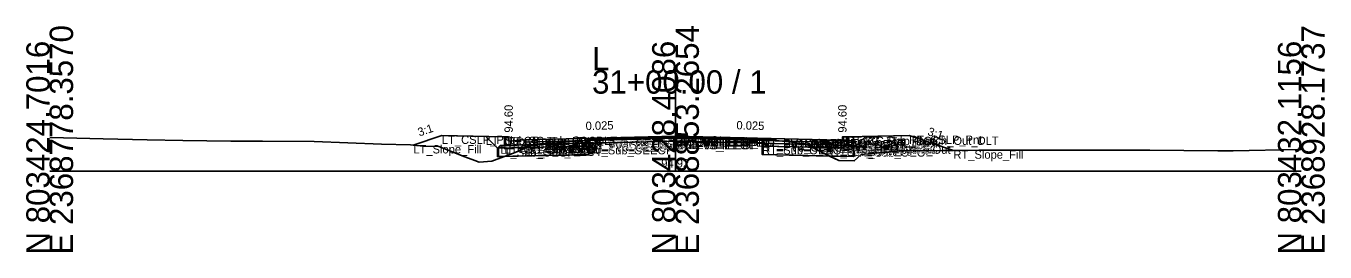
# Model space of a CAD drawing. Extents: x -26 to 8153, y -10 to 9520.
# Drawn here: x 1997.2 to 2152.8, y 4490.3 to 4517.4 of the extents above; entities that cross this region are included whole.
import ezdxf

# ---------------------------------------------------------------- set-up
doc = ezdxf.new("R2010")
doc.units = 0
for name, color, linetype in [('Exist CMT Pavement', 7, 'Continuous'), ('Exist Cross Section Cell', 7, 'Continuous'), ('Exist XS Center Line Elevation Label', 7, 'Continuous'), ('Exist XS Ground Line', 7, 'Continuous'), ('Prop CMT Conc Surface', 7, 'Continuous'), ('Prop CMT Concrete Structures', 7, 'Continuous'), ('Prop CMT Pvmt Course 1', 7, 'Continuous'), ('Prop CMT Pvmt Course 1 CG', 7, 'Continuous'), ('Prop CMT Pvmt Course 1 Wedge', 7, 'Continuous'), ('Prop CMT Pvmt Course 2', 7, 'Continuous'), ('Prop CMT Pvmt Course 2 Wedge', 7, 'Continuous'), ('Prop CMT Pvmt Course 3', 7, 'Continuous'), ('Prop CMT Pvmt Course 3 Wedge', 7, 'Continuous'), ('Prop CMT Pvmt Surface', 7, 'Continuous'), ('Prop CMT Pvmt Wedge Surface 1', 7, 'Continuous'), ('Prop CMT Pvmt Wedge Surface 2', 7, 'Continuous'), ('Prop CMT Pvmt Wedge Surface 3', 7, 'Continuous'), ('Prop CMT Shallow Undercut', 7, 'Continuous'), ('Prop CMT Shallow Undercut Boundary', 7, 'Continuous'), ('Prop CMT Slope Grass', 7, 'Continuous'), ('Prop CMT Subgrade Earthwork', 7, 'Continuous'), ('Prop XS Earthwork Shape', 7, 'Continuous'), ('Prop XS Hydro Elevations', 7, 'Continuous'), ('Prop XS SE Text', 7, 'Continuous'), ('Prop XS Side Slope Text', 7, 'Continuous'), ('Prop XS Subgrade Earthwork', 7, 'Continuous'), ('Scratch_Level_2', 7, 'Continuous'), ('Scratch_Level_6', 7, 'Continuous')]:
    doc.layers.add(name, color=color, linetype=linetype)

msp = doc.modelspace()

# ---------------------------------------------------------------- linework, layer by layer
at = {"layer": 'Exist CMT Pavement'}
for p, q in [((2068.35, 4503.79), (2074.82, 4503.93)), ((2074.82, 4503.93), (2077.37, 4503.91)), ((2077.37, 4503.91), (2085.38, 4503.83)), ((2064.58, 4503.69), (2068.35, 4503.79))]:
    msp.add_line(p, q, dxfattribs=at)
at = {"layer": 'Exist Cross Section Cell'}
for p, q in [((2075, 4500), (2075, 4512.07)), ((2000, 4500), (2075, 4500)), ((2075, 4500), (2150, 4500))]:
    msp.add_line(p, q, dxfattribs=at)
at = {"layer": 'Exist XS Ground Line'}
for p, q in [((2000, 4504.02), (2001.67, 4503.98)), ((2001.67, 4503.98), (2006.42, 4503.85)), ((2068.35, 4503.79), (2074.82, 4503.93)), ((2074.82, 4503.93), (2077.37, 4503.91)), ((2077.37, 4503.91), (2085.38, 4503.83)), ((2006.42, 4503.85), (2011.68, 4503.73)), ((2011.68, 4503.73), (2015.96, 4503.67)), ((2015.96, 4503.67), (2021.69, 4503.58)), ((2021.69, 4503.58), (2025.5, 4503.59)), ((2025.5, 4503.59), (2031.71, 4503.53)), ((2031.71, 4503.53), (2039.76, 4503.23)), ((2039.76, 4503.23), (2043.23, 4503.14)), ((2043.23, 4503.14), (2044.8, 4503)), ((2044.8, 4503), (2046.63, 4502.95)), ((2046.63, 4502.95), (2049.77, 4501.7)), ((2055.77, 4502.23), (2058.1, 4503.24)), ((2058.1, 4503.24), (2060.75, 4503.39)), ((2060.75, 4503.39), (2064.58, 4503.69)), ((2064.58, 4503.69), (2068.35, 4503.79)), ((2085.38, 4503.83), (2087.83, 4503.59)), ((2087.83, 4503.59), (2089.28, 4503.42)), ((2089.28, 4503.42), (2090.58, 4503.27)), ((2090.58, 4503.27), (2092.09, 4502.48)), ((2092.09, 4502.48), (2094.58, 4501.26)), ((2097.23, 4501.99), (2101.8, 4502.42)), ((2101.8, 4502.42), (2102.44, 4502.42)), ((2102.44, 4502.42), (2111.37, 4502.51)), ((2111.37, 4502.51), (2111.81, 4502.52)), ((2111.81, 4502.52), (2120.91, 4502.49)), ((2120.91, 4502.49), (2121.82, 4502.5)), ((2121.82, 4502.5), (2130.45, 4502.52)), ((2130.45, 4502.52), (2131.83, 4502.52)), ((2131.83, 4502.52), (2139.99, 4502.42)), ((2139.99, 4502.42), (2141.85, 4502.41)), ((2141.85, 4502.41), (2149.53, 4502.57)), ((2149.53, 4502.57), (2150, 4502.57)), ((2049.77, 4501.7), (2050.97, 4501.28)), ((2050.97, 4501.28), (2051.48, 4501.08)), ((2051.48, 4501.08), (2052.98, 4501.19)), ((2052.98, 4501.19), (2055.77, 4502.23)), ((2094.58, 4501.26), (2096.43, 4501.22)), ((2096.43, 4501.22), (2097.23, 4501.99))]:
    msp.add_line(p, q, dxfattribs=at)
at = {"layer": 'Prop CMT Conc Surface'}
for points in [[(2055, 4503.6), (2055, 4504.1), (2054.5, 4504.1)], [(2095, 4503.6), (2095, 4504.1), (2095.5, 4504.1)], [(2057, 4503.73), (2055, 4503.6)], [(2093, 4503.73), (2095, 4503.6)]]:
    msp.add_lwpolyline(points, dxfattribs=at)
at = {"layer": 'Prop CMT Concrete Structures'}
for points in [[(2057, 4503.73), (2055, 4503.6), (2055, 4504.1), (2054.5, 4504.1)], [(2054.5, 4504.1), (2054.5, 4503.08), (2057, 4503.14)], [(2093, 4503.73), (2095, 4503.6), (2095, 4504.1), (2095.5, 4504.1)], [(2095.5, 4504.1), (2095.5, 4503.08), (2093, 4503.14)], [(2057, 4503.14), (2057, 4503.73)], [(2093, 4503.14), (2093, 4503.73)]]:
    msp.add_lwpolyline(points, dxfattribs=at)
at = {"layer": 'Prop CMT Pvmt Course 1'}
for points in [[(2075, 4504.18), (2057, 4503.73)], [(2064.58, 4503.79), (2075, 4504.05)], [(2075, 4503.93), (2075, 4504.18)], [(2075, 4504.18), (2093, 4503.73)], [(2075, 4503.93), (2075, 4504.18)], [(2075, 4504.05), (2075, 4503.93), (2075, 4503.93)], [(2085.38, 4503.79), (2075, 4504.05)], [(2075, 4504.05), (2075, 4503.93), (2075, 4503.93)], [(2057, 4503.73), (2057, 4503.48)], [(2057, 4503.48), (2064.58, 4503.67)], [(2064.58, 4503.67), (2064.58, 4503.79)], [(2085.38, 4503.67), (2085.38, 4503.79)], [(2093, 4503.48), (2085.38, 4503.67)], [(2093, 4503.73), (2093, 4503.48)]]:
    msp.add_lwpolyline(points, dxfattribs=at)
at = {"layer": 'Prop CMT Pvmt Course 1 CG'}
for points in [[(2057, 4503.14), (2054, 4503.07), (2053.66, 4502.73)], [(2053.66, 4502.73), (2057, 4502.81)], [(2057, 4502.81), (2057, 4503.14)], [(2093, 4503.14), (2096, 4503.07), (2096.34, 4502.73)], [(2093, 4502.81), (2093, 4503.14)], [(2096.34, 4502.73), (2093, 4502.81)]]:
    msp.add_lwpolyline(points, dxfattribs=at)
at = {"layer": 'Prop CMT Pvmt Course 1 Wedge'}
for points in [[(2075, 4504.05), (2064.58, 4503.79)], [(2075, 4504.05), (2085.38, 4503.79)]]:
    msp.add_lwpolyline(points, dxfattribs=at)
at = {"layer": 'Prop CMT Pvmt Course 2'}
for points in [[(2064.58, 4503.67), (2057, 4503.48)], [(2057, 4503.48), (2057, 4503.15)], [(2057, 4503.15), (2064.58, 4503.34)], [(2064.58, 4503.34), (2064.58, 4503.67)], [(2085.38, 4503.34), (2085.38, 4503.67)], [(2085.38, 4503.67), (2093, 4503.48)], [(2093, 4503.15), (2085.38, 4503.34)], [(2093, 4503.48), (2093, 4503.15)]]:
    msp.add_lwpolyline(points, dxfattribs=at)
at = {"layer": 'Prop CMT Pvmt Course 2 Wedge'}
for points in [[(2075, 4503.93), (2064.58, 4503.67)], [(2075, 4503.93), (2085.38, 4503.67)]]:
    msp.add_lwpolyline(points, dxfattribs=at)
at = {"layer": 'Prop CMT Pvmt Course 3'}
for points in [[(2064.58, 4503.34), (2057, 4503.15)], [(2057, 4503.15), (2057, 4502.81)], [(2057, 4502.81), (2064.58, 4503)], [(2064.58, 4503), (2064.58, 4503.34)], [(2085.38, 4503.34), (2093, 4503.15)], [(2085.38, 4503), (2085.38, 4503.34)], [(2093, 4502.81), (2085.38, 4503)], [(2093, 4503.15), (2093, 4502.81)]]:
    msp.add_lwpolyline(points, dxfattribs=at)
at = {"layer": 'Prop CMT Pvmt Course 3 Wedge'}
for points in [[(2075, 4503.6), (2064.58, 4503.34)], [(2075, 4503.6), (2085.38, 4503.34)]]:
    msp.add_lwpolyline(points, dxfattribs=at)
at = {"layer": 'Prop CMT Pvmt Surface'}
for points in [[(2075, 4504.18), (2057, 4503.73)], [(2075, 4504.18), (2093, 4503.73)]]:
    msp.add_lwpolyline(points, dxfattribs=at)
at = {"layer": 'Prop CMT Pvmt Wedge Surface 1'}
for points in [[(2075, 4504.05), (2064.58, 4503.79)], [(2075, 4504.05), (2085.38, 4503.79)], [(2057, 4503.48), (2057, 4503.73)], [(2064.58, 4503.67), (2057, 4503.48)], [(2064.58, 4503.79), (2064.58, 4503.67)], [(2085.38, 4503.79), (2085.38, 4503.67)], [(2085.38, 4503.67), (2093, 4503.48)], [(2093, 4503.48), (2093, 4503.73)]]:
    msp.add_lwpolyline(points, dxfattribs=at)
at = {"layer": 'Prop CMT Pvmt Wedge Surface 2'}
for points in [[(2075, 4503.93), (2057, 4503.48)], [(2075, 4503.93), (2093, 4503.48)], [(2057, 4503.48), (2057, 4503.73)], [(2093, 4503.48), (2093, 4503.73)]]:
    msp.add_lwpolyline(points, dxfattribs=at)
at = {"layer": 'Prop CMT Pvmt Wedge Surface 3'}
for points in [[(2057, 4503.15), (2057, 4503.73)], [(2075, 4503.6), (2057, 4503.15)], [(2075, 4503.6), (2093, 4503.15)], [(2093, 4503.15), (2093, 4503.73)]]:
    msp.add_lwpolyline(points, dxfattribs=at)
at = {"layer": 'Prop CMT Shallow Undercut'}
for points in [[(2064.58, 4503), (2064.58, 4502), (2054.48, 4501.75), (2055.77, 4502.23), (2057.12, 4502.82)], [(2093.46, 4501.8), (2085.38, 4502), (2085.38, 4503), (2091.37, 4502.85), (2092.09, 4502.48)]]:
    msp.add_lwpolyline(points, close=True, dxfattribs=at)
at = {"layer": 'Prop CMT Shallow Undercut Boundary'}
for p, q in [((2053.66, 4502.73), (2064.58, 4503)), ((2053.66, 4502.73), (2053.66, 4501.73)), ((2064.58, 4503), (2064.58, 4502)), ((2085.38, 4503), (2085.38, 4502)), ((2085.38, 4503), (2096.34, 4502.73)), ((2096.34, 4502.73), (2096.34, 4501.73)), ((2064.58, 4502), (2053.66, 4501.73)), ((2096.34, 4501.73), (2085.38, 4502))]:
    msp.add_line(p, q, dxfattribs=at)
at = {"layer": 'Prop CMT Slope Grass'}
for points in [[(2054.5, 4504.1), (2047, 4504.25), (2043.58, 4503.11)], [(2095.5, 4504.1), (2103, 4504.25), (2108.3, 4502.48)]]:
    msp.add_lwpolyline(points, dxfattribs=at)
at = {"layer": 'Prop CMT Subgrade Earthwork'}
for points in [[(2057, 4502.81), (2053.66, 4502.73), (2052.25, 4504.14)], [(2093, 4502.81), (2096.34, 4502.73), (2097.75, 4504.14)], [(2064.58, 4503), (2057, 4502.81)], [(2064.58, 4503), (2064.6, 4503.69)], [(2085.38, 4503), (2085.37, 4503.83)], [(2085.38, 4503), (2093, 4502.81)]]:
    msp.add_lwpolyline(points, dxfattribs=at)
at = {"layer": 'Prop XS Earthwork Shape'}
for points in [[(2046.63, 4502.95), (2049.77, 4501.7), (2050.97, 4501.28), (2051.48, 4501.08), (2052.98, 4501.19), (2054.48, 4501.75), (2053.66, 4501.73), (2053.66, 4502.73), (2052.25, 4504.14), (2047, 4504.25), (2043.58, 4503.11), (2044.8, 4503)], [(2097.23, 4501.99), (2101.8, 4502.42), (2102.44, 4502.42), (2108.3, 4502.48), (2103, 4504.25), (2097.75, 4504.14), (2096.34, 4502.73), (2096.34, 4501.73), (2093.46, 4501.8), (2094.58, 4501.26), (2096.43, 4501.22)], [(2054.48, 4501.75), (2053.66, 4501.73), (2053.66, 4502.73), (2057, 4502.81), (2057.12, 4502.82), (2055.77, 4502.23)], [(2054.48, 4501.75), (2055.77, 4502.23), (2057.12, 4502.82), (2064.58, 4503), (2064.58, 4502)], [(2060.75, 4503.39), (2064.58, 4503.69), (2064.6, 4503.69), (2064.58, 4503), (2057.12, 4502.82), (2058.1, 4503.24)], [(2085.38, 4503), (2091.37, 4502.85), (2090.58, 4503.27), (2089.28, 4503.42), (2087.83, 4503.59), (2085.38, 4503.83), (2085.37, 4503.83)], [(2085.38, 4503), (2091.37, 4502.85), (2092.09, 4502.48), (2093.46, 4501.8), (2085.38, 4502)], [(2091.37, 4502.85), (2092.09, 4502.48), (2093.46, 4501.8), (2096.34, 4501.73), (2096.34, 4502.73), (2093, 4502.81)]]:
    msp.add_lwpolyline(points, close=True, dxfattribs=at)
at = {"layer": 'Prop XS Subgrade Earthwork'}
for p, q in [((2053.66, 4502.73), (2064.58, 4503)), ((2085.38, 4503), (2096.34, 4502.73))]:
    msp.add_line(p, q, dxfattribs=at)
at = {"layer": 'Scratch_Level_6'}
for points in [[(2064.58, 4503), (2064.58, 4502), (2054.48, 4501.75), (2055.77, 4502.23), (2057.12, 4502.82)], [(2093.46, 4501.8), (2085.38, 4502), (2085.38, 4503), (2091.37, 4502.85), (2092.09, 4502.48)]]:
    msp.add_lwpolyline(points, close=True, dxfattribs=at)

# ---------------------------------------------------------------- texts
at = {"layer": 'Exist Cross Section Cell'}
for s, p in [('E 2368778.3570', (2002.8, 4490)), ('E 2368853.2654', (2077.8, 4490)), ('E 2368928.1737', (2152.8, 4490)), ('N 803424.7016', (2000, 4490)), ('N 803428.4086', (2075, 4490)), ('N 803432.1156', (2150, 4490))]:
    msp.add_text(s, height=2.8, rotation=90, dxfattribs=at).set_placement(p)
for s, p in [('L', (2065, 4512.07)), ('31+00.00 / 1', (2065, 4509.27))]:
    msp.add_text(s, height=2.8, dxfattribs=at).set_placement(p)
at = {"layer": 'Exist XS Center Line Elevation Label'}
msp.add_text('94.92', height=1, dxfattribs=at).set_placement((2073.29, 4500.42))
at = {"layer": 'Prop XS Hydro Elevations'}
for p in [(2055.5, 4504.6), (2095.5, 4504.6)]:
    msp.add_text('94.60', height=1, rotation=90, dxfattribs=at).set_placement(p)
at = {"layer": 'Prop XS SE Text'}
for rotation, p in [(1.4321, (2064.24, 4504.91)), (358.5679, (2082.29, 4505))]:
    msp.add_text('0.025', height=1, rotation=rotation, dxfattribs=at).set_placement(p)
at = {"layer": 'Prop XS Side Slope Text'}
for rotation, p in [(18.4349, (2044.3, 4504.14)), (341.5651, (2105.13, 4504.33))]:
    msp.add_text('3:1', height=1, rotation=rotation, dxfattribs=at).set_placement(p)
at = {"layer": 'Scratch_Level_2'}
for s, p in [('LT_CSLP_Pnt', (2047, 4503.25)), ('LT_Sub_Trench_Out_DLT', (2052.25, 4503.14)), ('LT_CG_Top_BOC', (2054.5, 4503.1)), ('LT_CG_Top_Face', (2055, 4503.1)), ('PV1_PGL', (2075, 4503.18)), ('RT_PV1_IEEOP', (2075, 4503.05)), ('LT_PV1_IEEOP', (2075, 4503.05)), ('RT_PV2_IEEOP', (2075, 4502.93)), ('RT_PV_IEEOP_EG', (2075, 4502.92)), ('LT_PV2_IEEOP', (2075, 4502.93)), ('PV2_PGL', (2075, 4502.93)), ('LT_PV_IEEOP_EG', (2075, 4502.92)), ('RT_PV_Sub_Tie_Out', (2085.37, 4502.83)), ('RT_CG_Top_Face', (2095, 4503.1)), ('RT_CG_Top_BOC', (2095.5, 4503.1)), ('RT_Sub_Trench_Out_DLT', (2097.75, 4503.14)), ('RT_CSLP_Pnt', (2103, 4503.25)), ('LT_Slope_Fill', (2043.58, 4502.11)), ('LT_Sub_OEOP', (2053.66, 4501.73)), ('LT_CG1_Shelf_Out', (2054, 4502.07)), ('LT_CG_Bot_BOC', (2054.5, 4502.08)), ('LT_CG_Top_Gut', (2055, 4502.6)), ('LT_PV1_OEOT', (2057, 4502.73)), ('LT_PV2_OEOT', (2057, 4502.48)), ('LT_PV3_OEOT', (2057, 4502.15)), ('LT_CG_Bot_IE', (2057, 4502.14)), ('LT_Sub_OEOT', (2057, 4501.81)), ('LT_PV1_OEEOP', (2064.58, 4502.79)), ('LT_PV_OEEOP_EG', (2064.58, 4502.69)), ('LT_PV2_OEEOP', (2064.58, 4502.67)), ('LT_PV3_OEEOP', (2064.58, 4502.34)), ('LT_Sub_OEEOP', (2064.58, 4502)), ('LT_PV_Sub_Tie_Out', (2064.6, 4502.69)), ('RT_PV3_IEEOP', (2075, 4502.6)), ('LT_PV3_IEEOP', (2075, 4502.6)), ('RT_PV_OEEOP_EG', (2085.38, 4502.83)), ('RT_PV1_OEEOP', (2085.38, 4502.79)), ('RT_PV2_OEEOP', (2085.38, 4502.67)), ('RT_PV3_OEEOP', (2085.38, 4502.34)), ('RT_Sub_OEEOP', (2085.38, 4502)), ('RT_PV1_OEOT', (2093, 4502.73)), ('RT_PV2_OEOT', (2093, 4502.48)), ('RT_PV3_OEOT', (2093, 4502.15)), ('RT_CG_Bot_IE', (2093, 4502.14)), ('RT_Sub_OEOT', (2093, 4501.81)), ('RT_CG_Top_Gut', (2095, 4502.6)), ('RT_CG_Bot_BOC', (2095.5, 4502.08)), ('RT_CG1_Shelf_Out', (2096, 4502.07)), ('RT_Sub_OEOP', (2096.34, 4501.73)), ('RT_Slope_Fill', (2108.3, 4501.48))]:
    msp.add_text(s, height=1, dxfattribs=at).set_placement(p)

doc.saveas('drawing.dxf')
